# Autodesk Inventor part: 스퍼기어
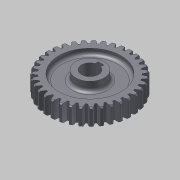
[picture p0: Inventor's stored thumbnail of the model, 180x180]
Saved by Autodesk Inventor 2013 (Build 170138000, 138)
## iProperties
Created: 2013-08
Part Number: 스퍼기어
Material: 강
Document SubType Name: Modeling
Designer: 한국산업디자인학원
Categories: <?xml version="1.0" encoding="UTF-16"?> <MemberInstance><Categories><FamilyTemplate><FamilyTemplateParameter ValueType="xs:double" Id="1" ObjectReferenceKey="da
Density: 1 g/cm^3
CustomPartVersion: 1
Author: 한국산업디자인학원
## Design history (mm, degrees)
sketch "Sketch1"
  geometry: C1 r 37 at (0, 0)
  constraints: 1 centre point
  dimensions: "d0" = 74 diameter of C1 (= da_da)
extrude "Extrusion1" new body sketch "Sketch1" distance "d1" = 15 (= da_b); taper "d2" = 0 deg
workplane "Work Plane2"
feature "피치 지름" dims "d4" = 10, "d5" = 0
workplane "Work Plane8"
workplane "Work Plane9"
feature "스퍼 기어" dims "da_b" = 15, "da_d" = 70, "da_aw" = 70, "da_da" = 74, "da_df" = 65, "da_dw" = 70, angle "da_beta" = 0 deg, "da_lefttooth" = 0, "da_righttooth" = 0
sketch "스케치3"
  geometry: L1 (0, 18)-(0, -13); L2 (0, -13)-(12.5, -13); L3 (12.5, -13)-(12.5, 18); L4 (12.5, 18)-(0, 18); 1 further point
  constraints: 8 end point, 2 perpendicular, 1 parallel, 1 vertical, 1 vertical alignment
  dimensions: "d49" = 31 distance of L1.start L1.end; "d51" = 18 distance of L1.start point (0, 0); "d52" = 25 diameter of L3 L1
revolve "회전1" sketch "스케치3" stored, may be unused: angle "d53" = 90 deg
sketch "스케치4"
  geometry: L1 (-12.5, 18)-(12.5, 18) reference; L2 (-12.5, -13)-(12.5, -13) reference; L3 (0, 18)-(0, -13); L4 (0, -13)-(7.5, -13); L5 (7.5, -13)-(7.5, 18); L6 (7.5, 18)-(0, 18); L7 (12.5, 18)-(12.5, 15) reference; L8 (12.5, 0)-(12.5, -13) reference; L9 (12.5, 15)-(27.5, 15); L10 (27.5, 15)-(27.5, 10); L11 (27.5, 10)-(12.5, 10); L12 (12.5, 10)-(12.5, 15); L13 (12.5, 0)-(27.5, 0); L14 (27.5, 0)-(27.5, 5); L15 (27.5, 5)-(12.5, 5); L16 (12.5, 5)-(12.5, 0); 1 further point
  constraints: 24 end point, 4 parallel, 3 collinear, 3 perpendicular, 2 horizontal, 2 midpoint, 2 point on line
  dimensions: "d54" = 15 diameter of L5 L3; "d55" = 55 diameter of L10 L3; "d56" = 5 distance of L9.end L10.end
revolve "회전2" sketch "스케치4" stored, may be unused: angle "d57" = 90 deg
sketch "스케치5"
  geometry: L1 (-7.5, -13)-(-7.5, 18) reference; L2 (-12.5, 18)-(12.5, 18) reference; L3 (-12.5, -13)-(12.5, -13) reference; L4 (0, 18)-(9.8, 18); L5 (9.8, 18)-(9.8, -13); L6 (9.8, -13)-(0, -13); L7 (0, -13)-(0, 18); 1 further point
  constraints: 8 end point, 2 parallel, 1 horizontal, 1 midpoint, 1 perpendicular, 1 point on line
  dimensions: "d58" = 17.3 distance between parallel lines of L1 L5
extrude "돌출2" cut sketch "스케치5" stored distance "d59" = 5; taper "d60" = 0 deg
fillet "모깎기1" dims "d61" = 3
chamfer "모따기1" distance "d62" = 1; stored, may be unused: second distance "d63" = 2, angle "d64" = 45 deg
chamfer "모따기2" distance "d65" = 1; stored, may be unused: second distance "d66" = 2, angle "d67" = 45 deg
body "Solid1"
sketch "Sketch2"
  geometry: C1 r 37 at (0, 0) reference; C2 r 35 at (0, 0)
  constraints: 1 centre point, 1 coincident
  dimensions: "d3" = 70 diameter of C2 (= da_dw)
body "Srf1"
other parameters: "d17" = 0, "d34" = 0.8976 (computed from da_z), "d39" = 0, "d41" = 0, "d47" = 0, "d48" = 0
